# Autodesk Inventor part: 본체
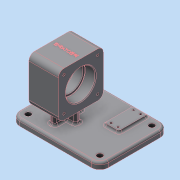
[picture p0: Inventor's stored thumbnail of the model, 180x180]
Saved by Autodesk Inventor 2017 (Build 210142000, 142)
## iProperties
Created: 2019-09
Part Number: 본체
Material: 알루미늄 6061
Document SubType Name: Modeling
Designer: mduedu
Density: 2.71 g/cm^3
Mass: 636.366 g
Surface Area: 520.125 cm^2
Volume: 234.821 cm^3
Appearance: 기본값
Author: mduedu
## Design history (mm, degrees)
sketch "스케치1"
  geometry: L1 (42, -62)-(-84, -62); L2 (-84, -62)-(-84, 36); L3 (-84, 36)-(42, 36); L4 (42, 36)-(42, -62); 1 further point
  constraints: 8 end point, 2 parallel, 1 horizontal, 1 perpendicular
  dimensions: "d0" = 36 distance from line of L3 point (0, 0); "d1" = 98 distance of L1.end L2.end; "d2" = 42 distance from line of L4 point (0, 0); "d3" = 126 distance of L2.end L3.end
extrude "돌출1" new body sketch "스케치1" distance "d4" = 9; taper "d5" = 0 deg
sketch "스케치2"
  geometry: L1 (0, -62)-(0, 36) reference; L2 (27, -32)-(91, -32); L3 (91, -32)-(91, 32); L4 (91, 32)-(27, 32); L5 (27, 32)-(27, -32); L6 (27, -32)-(91, 32); L7 (91, -32)-(27, 32); 3 further points
  constraints: 12 end point, 3 midpoint, 2 parallel, 1 horizontal, 1 horizontal alignment, 1 perpendicular
  dimensions: "d87" = 64 distance of L4.end L3.end; "d88" = 64 distance of L3.end L2.end; "d89" = 59 distance from line of point (59, 0) L1
extrude "돌출2" join sketch "스케치2" stored distance "d8" = 42; taper "d9" = 0 deg
sketch "스케치3"
  geometry: L1 (-17, 4)-(17, 4); L2 (17, 4)-(17, -4); L3 (17, -4)-(-17, -4); L4 (-17, -4)-(-17, 4); L5 (-4, 20)-(4, 20); L6 (4, 20)-(4, -20); L7 (4, -20)-(-4, -20); L8 (-4, -20)-(-4, 20); 5 further points
  constraints: 16 end point, 4 midpoint, 4 parallel, 2 horizontal, 2 horizontal alignment, 2 perpendicular, 2 vertical alignment
  dimensions: "d10" = 8 distance of L5.start L5.end; "d12" = 8 distance of L1.end L2.end; "d13" = 34 distance of L2.end L3.end; "d14" = 40 distance of L5.end L6.end
extrude "돌출3" join sketch "스케치3" stored distance "d15" = 42; taper "d16" = 0 deg
sketch "스케치4"
  geometry: L1 (-32, 91)-(-32, 27) reference; L2 (32, 91)-(-32, 91) reference; L3 (32, 27)-(32, 91) reference; L4 (-32, 27)-(32, 27) reference; C1 r 21 at (0, 59); 3 further points
  constraints: 2 midpoint, 1 centre point, 1 horizontal alignment, 1 vertical alignment
  dimensions: "d17" = 42 diameter of C1
extrude "돌출4" cut sketch "스케치4" distance "d18" = 15; taper "d19" = 0 deg
hole "구멍1" diameter "d22" = 36; stored, may be unused: countersink angle "d26" = 90 deg, drill point angle "d28" = 118 deg; dims "d20" = 10, "d21" = 10, "d23" = 6, "d24" = 4, "d25" = 2, "d27" = 8
fillet "모깎기1" dims "d29" = 0.3
chamfer "모따기1" distance "d30" = 1; stored, may be unused: second distance "d31" = 2, angle "d32" = 45 deg
fillet "모깎기9" dims "d90" = 8
sketch "스케치11"
  geometry: L1 (-24, 27)-(24, 27) reference; L2 (32, 35)-(32, 83) reference; L3 (24, 91)-(-24, 91) reference; L4 (-32, 83)-(-32, 35) reference; C1 r 22 at (0, 59) reference; A1 r 8 centre (-24, 35) between (-32, 35) and (-24, 27) reference; A2 r 8 centre (24, 35) between (24, 27) and (32, 35) reference; A3 r 8 centre (24, 83) between (32, 83) and (24, 91) reference; A4 r 8 centre (-24, 83) between (-24, 91) and (-32, 83) reference; 5 further points
  constraints: 4 coincident
hole "구멍6" sketch "스케치11" at (-24, 83), (24, 83), (24, 35), (-24, 35) diameter "d91" = 3.242; stored, may be unused: countersink angle "d95" = 90 deg, drill point angle "d97" = 118 deg; dims "d92" = 8, "d93" = 4, "d94" = 2, "d96" = 10
fillet "모깎기2" dims "d44" = 12
sketch "스케치6"
  geometry: L1 (-42, 50)-(-42, -24) reference; L2 (-30, -36)-(72, -36) reference; L3 (84, -24)-(84, 50) reference; L4 (72, 62)-(-30, 62) reference; L5 (17, 4)-(17, -4) reference; L6 (17, -4)-(4, -4) reference; L7 (4, -4)-(4, -20) reference; L8 (4, -20)-(-4, -20) reference; L9 (-4, -20)-(-4, -4) reference; L10 (-4, -4)-(-17, -4) reference; L11 (-17, -4)-(-17, 4) reference; L12 (-17, 4)-(-4, 4) reference; L13 (-4, 4)-(-4, 20) reference; L14 (-4, 20)-(4, 20) reference; L15 (4, 20)-(4, 4) reference; L16 (4, 4)-(17, 4) reference; A1 r 12 centre (-30, 50) between (-30, 62) and (-42, 50) reference; A2 r 12 centre (-30, -24) between (-42, -24) and (-30, -36) reference; A3 r 12 centre (72, -24) between (72, -36) and (84, -24) reference; A4 r 12 centre (72, 50) between (84, 50) and (72, 62) reference; 5 further points
  constraints: 4 coincident
hole "구멍3" sketch "스케치6" at (-30, 50), (72, 50), (72, -24), (-30, -24) diameter "d45" = 8; stored, may be unused: countersink angle "d49" = 90 deg, drill point angle "d51" = 118 deg; dims "d46" = 8, "d47" = 4, "d48" = 2, "d50" = 10
sketch "스케치7"
  geometry: L1 (38, 57)-(58, 57); L2 (58, 57)-(58, 17); L3 (58, 17)-(38, 17); L4 (38, 17)-(38, 57); L5 (72, 62)-(-30, 62) reference; 3 further points
  constraints: 8 end point, 2 midpoint, 2 parallel, 1 horizontal, 1 perpendicular
  dimensions: "d52" = 48 horizontal distance of point (48, 57) point (0, 0); "d53" = 20 distance of L1.start L1.end; "d54" = 40 distance of L1.end L2.end; "d55" = 25 distance from line of point (38, 37) L5
extrude "돌출5" join sketch "스케치7" distance "d56" = 3; taper "d57" = 0 deg
fillet "모깎기3" dims "d58" = 3
fillet "모깎기4" dims "d59" = 3
fillet "모깎기5" dims "d60" = 3
fillet "모깎기6" dims "d61" = 3
fillet "모깎기7" dims "d62" = 3
fillet "모깎기8" dims "d63" = 3
sketch "스케치8"
  geometry: L1 (72, 62)-(58.317, 62) reference; L2 (84, -24)-(84, 50) reference; C1 r 1.5 at (43, 53); C2 r 1.5 at (53, 21); 1 further point
  constraints: 2 centre point, 1 equal radius
  dimensions: "d64" = 3 diameter of C1; "d65" = 9 distance from line of C1.centre L1; "d66" = 32 vertical distance of C2.centre C1.centre; "d67" = 10 horizontal distance of C2.centre C1.centre; "d68" = 31 distance from line of L2 C2.centre
hole "구멍4" sketch "스케치8" at (43, 53), (53, 21) diameter "d69" = 3; stored, may be unused: countersink angle "d73" = 90 deg, drill point angle "d75" = 118 deg; dims "d70" = 8, "d71" = 4, "d72" = 2, "d74" = 6
sketch "스케치9"
  geometry: C1 r 1.5 at (43, 53) reference; C2 r 1.5 at (53, 21) reference; 3 further points
  constraints: 2 horizontal alignment, 2 vertical alignment
hole "구멍5" sketch "스케치9" at (53, 53), (43, 21) diameter "d76" = 3.242; stored, may be unused: countersink angle "d80" = 90 deg, drill point angle "d82" = 118 deg; dims "d77" = 6, "d78" = 4, "d79" = 2, "d81" = 8
sketch "스케치10"
  geometry: 2 further points
  constraints: 1 coincident, 1 other
feature "엠보싱1" sketch "스케치10" dims "d0" = 36, "d1" = 98, "d2" = 42, "d3" = 126, "d12" = 8, "d13" = 34, "d85" = 0.5, "d86" = 0
node "솔리드1"
mirror "대칭1"
mirror "대칭2"
node "투영된 루프1"
node "투영된 루프2"
